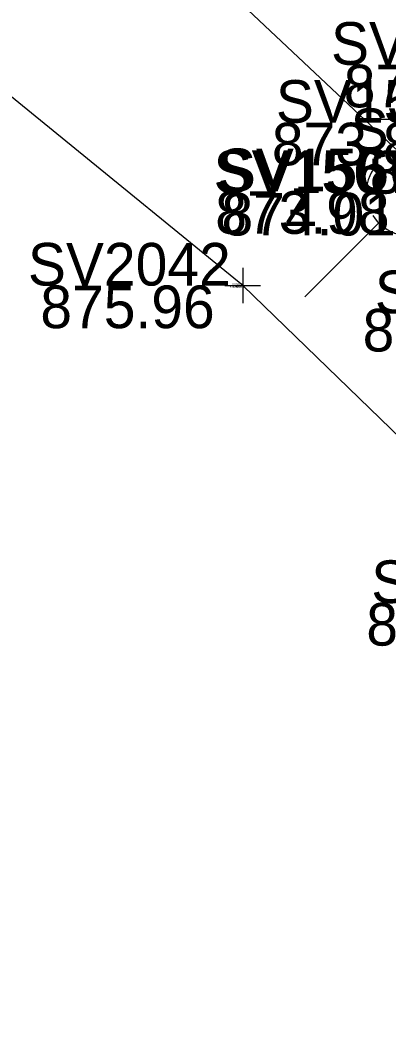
# Model space of a CAD drawing. Extents: x 1475918 to 1480402, y 379235 to 383359.
# Drawn here: x 1480117.53 to 1480127.89, y 379405.99 to 379434.1 of the extents above; entities that cross this region are included whole.
import ezdxf

# ---------------------------------------------------------------- set-up
doc = ezdxf.new("R2010")
doc.units = 0
for name, color, linetype in [('PV_X_Walk', 7, 'Continuous'), ('SV_X_Break_Lines', 7, 'Continuous'), ('SV_X_Shot_Marker', 7, 'Continuous'), ('SV_X_Text_Comment', 7, 'Continuous'), ('SV_X_Text_Elevation', 7, 'Continuous'), ('SV_X_Text_Name', 7, 'Continuous'), ('UT_X_Water_Cells', 7, 'Continuous')]:
    doc.layers.add(name, color=color, linetype=linetype)

msp = doc.modelspace()

# ---------------------------------------------------------------- linework, layer by layer
at = {"layer": 'PV_X_Walk'}
msp.add_lwpolyline([(1480035.484, 379289.224), (1480050.568, 379305.437), (1480062.335, 379317.896), (1480064.038, 379319.719), (1480070.805, 379327.066), (1480078.054, 379334.946), (1480079.953, 379336.866), (1480094.208, 379352.393), (1480112.048, 379371.575), (1480117.348, 379377.211), (1480119.911, 379379.906), (1480121.511, 379381.77), (1480134.604, 379395.58), (1480136.695, 379398.148), (1480138.778, 379401.149), (1480140.004, 379404.725), (1480140.577, 379408.06), (1480140.982, 379411.311), (1480140.871, 379414.584), (1480140.225, 379417.636), (1480139.184, 379419.586), (1480133.124, 379425.845), (1480132.903, 379425.968), (1480114.834, 379442.96)], dxfattribs=at)
at = {"layer": 'SV_X_Break_Lines'}
msp.add_lwpolyline([(1480127.721, 379395.358), (1480131.799, 379398.039), (1480133.273, 379401.352), (1480135.459, 379407.36), (1480135.6, 379409.555), (1480135.793, 379413.076), (1480135.014, 379415.657), (1480133.026, 379417.684), (1480123.803, 379426.624), (1480113.121, 379435.343), (1480106.984, 379440.926), (1480103.73, 379443.918), (1480102.529, 379445.074), (1480100.774, 379445.951), (1480096.595, 379444.059), (1480092.174, 379441.029), (1480086.377, 379436.591)], dxfattribs=at)
at = {"layer": 'SV_X_Shot_Marker'}
for p, q in [((1480123.803, 379427.124), (1480123.803, 379426.124)), ((1480123.303, 379426.624), (1480124.303, 379426.624)), ((1480123.821, 379426.606), (1480123.785, 379426.641)), ((1480123.786, 379426.606), (1480123.82, 379426.642)), ((1480123.803, 379426.624), (1480123.803, 379426.624)), ((1480123.803, 379426.624), (1480123.803, 379426.624))]:
    msp.add_line(p, q, dxfattribs=at)
at = {"layer": 'UT_X_Water_Cells'}
for p, q in [((1480129.678, 379431.298), (1480127.278, 379431.298)), ((1480127.633, 379428.386), (1480125.553, 379426.308))]:
    msp.add_line(p, q, dxfattribs=at)
for start, end in [(140.021, 184.0629), (211.8788, 255.8479)]:
    msp.add_arc((1480128.48, 379429.234), 1.2, start, end, dxfattribs=at)

# ---------------------------------------------------------------- texts
at = {"layer": 'SV_X_Text_Comment'}
msp.add_text('B', height=0.06, dxfattribs=at).set_placement((1480123.803, 379426.564))
at = {"layer": 'SV_X_Text_Elevation'}
for s, height, p in [('874.13', 1.2, (1480126.647, 379431.643)), ('873.85', 1.2, (1480124.623, 379430.01)), ('873.94', 1.2, (1480127.379, 379429.213)), ('873.98', 1.2, (1480123.029, 379428.082)), ('874.01', 1.2, (1480123.206, 379428.034)), ('875.96', 1.2, (1480118.106, 379425.424)), ('875.9616', 0.06, (1480123.437, 379426.564)), ('875.96', 0.06, (1480123.518, 379426.564)), ('874.03', 1.2, (1480127.178, 379424.768)), ('876.09', 1.2, (1480127.281, 379416.484))]:
    msp.add_text(s, height=height, dxfattribs=at).set_placement(p)
at = {"layer": 'SV_X_Text_Name'}
for s, height, p in [('SV1565', 1.2, (1480126.288, 379432.843)), ('SV1568', 1.2, (1480124.737, 379431.21)), ('SV2008', 1.2, (1480126.84, 379430.413)), ('SV1567', 1.2, (1480122.982, 379429.234)), ('SV1566', 1.2, (1480123.105, 379429.282)), ('SV2042', 1.2, (1480117.756, 379426.624)), ('SV1902', 1.2, (1480127.522, 379425.845)), ('SV2042', 0.06, (1480123.501, 379426.624)), ('SV2042', 0.06, (1480123.501, 379426.624)), ('SV2041', 1.2, (1480127.421, 379417.684))]:
    msp.add_text(s, height=height, dxfattribs=at).set_placement(p)

doc.saveas('drawing.dxf')
